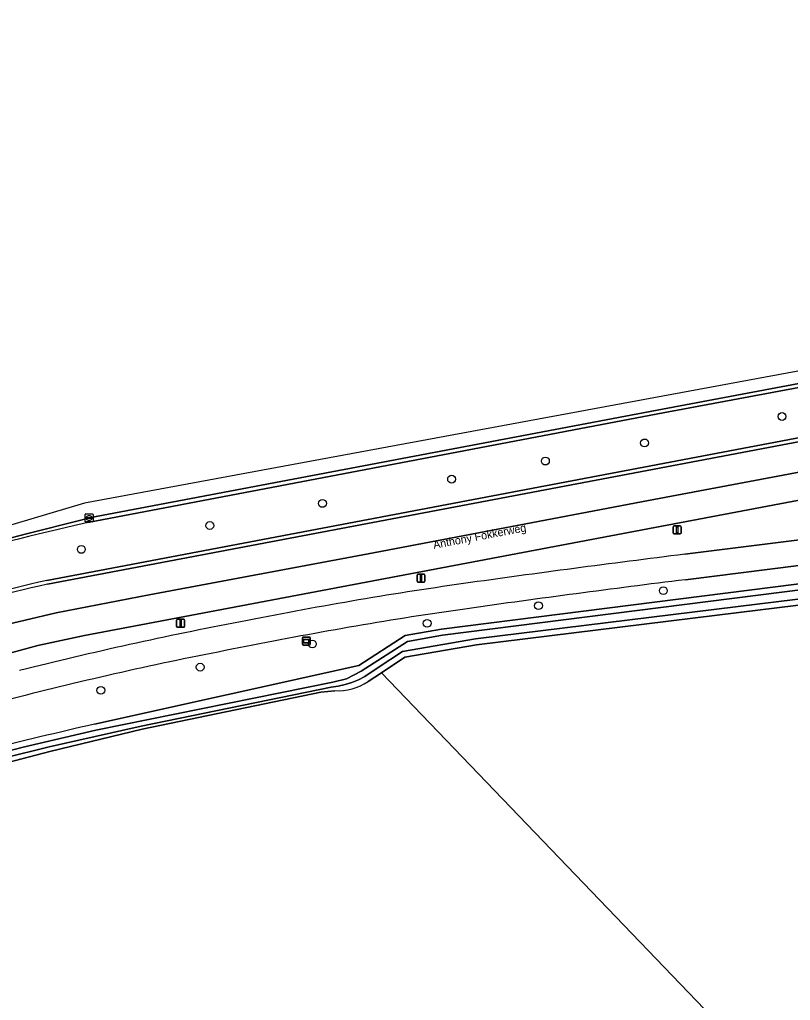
# Model space of a CAD drawing. Extents: x 157132 to 159279, y 384991 to 386650.
# Drawn here: x 157669 to 157765.4, y 386347.4 to 386470 of the extents above; entities that cross this region are included whole.
import ezdxf

# ---------------------------------------------------------------- set-up
doc = ezdxf.new("R2010")
doc.units = 0
for name, color, linetype in [('IMGEO_Berm_groen', 7, 'Continuous'), ('IMGEO_Berm_open', 7, 'Continuous'), ('IMGEO_Boom', 7, 'Continuous'), ('IMGEO_Bouwland', 7, 'Continuous'), ('IMGEO_Fietspad_open', 7, 'Continuous'), ('IMGEO_Groenvoorziening', 7, 'Continuous'), ('IMGEO_Kolk', 7, 'Continuous'), ('IMGEO_Lichtmast', 7, 'Continuous'), ('IMGEO_Loofbos', 7, 'Continuous'), ('IMGEO_Oever', 7, 'Continuous'), ('IMGEO_Openbare_ruimte_label', 7, 'Continuous'), ('IMGEO_Rijbaan_regionaal_gesloten', 7, 'Continuous'), ('IMGEO_Verklikker', 7, 'Continuous'), ('IMGEO_Waterloop', 7, 'Continuous')]:
    doc.layers.add(name, color=color, linetype=linetype)

msp = doc.modelspace()

# ---------------------------------------------------------------- linework, layer by layer
at = {"layer": 'IMGEO_Berm_groen'}
for points in [[(157813.78, 386432.88), (157748.87, 386420.72), (157677.57, 386407.16)], [(157672.45, 386399.91), (157816.05, 386427.15)], [(157843.77, 386421.91), (157840.21, 386420.94), (157837.53, 386420.52), (157807.76, 386417.47), (157804.84, 386417.18), (157677.17, 386393.04), (157671.33, 386391.76), (157661.82, 386389.18), (157654.52, 386387.21), (157643.11, 386383.56), (157641.3, 386382.98), (157629.56, 386378.95), (157619.91, 386375.39), (157605.44, 386369.88), (157598.41, 386367.06), (157586.87, 386361.94)], [(157752.22, 386403.2), (157786.88, 386407.53), (157833.7, 386413.41)]]:
    msp.add_lwpolyline(points, dxfattribs=at)
for centre, radius, start, end in [((157790.4, 385918.61), 501.41, 103.0044, 107.6634), ((157993.4, 384480.42), 1937.84, 97.14941, 97.97507), ((157771.77, 385969.6), 441.63, 102.9972, 107.3297), ((157794.41, 385908.3), 496.16, 98.0956, 101.363), ((157786.26, 385923.76), 479.43, 100.7721, 104.1519)]:
    msp.add_arc(centre, radius, start, end, dxfattribs=at)
at = {"layer": 'IMGEO_Berm_open'}
for points in [[(157921.21, 386470.01), (157894.12, 386457.52), (157865.93, 386446.88), (157837.1, 386438.58), (157813.68, 386433.39), (157748.77, 386421.2), (157677.74, 386407.72), (157676.87, 386407.48), (157669.9, 386405.73), (157663.33, 386404.02), (157660.03, 386403.12), (157650.63, 386400.53), (157647.58, 386399.62), (157640.8, 386397.6), (157638.12, 386396.74), (157629.98, 386394.14), (157623.21, 386391.87), (157613.38, 386388.34), (157610.21, 386387.16), (157600.92, 386383.53), (157598.68, 386382.58), (157589.94, 386378.98)], [(157677.57, 386407.16), (157748.87, 386420.72), (157813.78, 386432.88)], [(157672.51, 386399.46), (157816.13, 386426.67), (157825.96, 386428.65), (157835.9, 386430.97)], [(157825.85, 386429.16), (157816.05, 386427.15), (157672.45, 386399.91)]]:
    msp.add_lwpolyline(points, dxfattribs=at)
for centre, radius, start, end in [((157790.4, 385918.61), 501.41, 103.0044, 107.6634), ((157771.77, 385969.6), 441.63, 102.9972, 107.3297), ((157770.41, 385975.21), 435.39, 102.9944, 107.3754)]:
    msp.add_arc(centre, radius, start, end, dxfattribs=at)
at = {"layer": 'IMGEO_Boom'}
for centre in [(157764.38, 386420.4), (157747.19, 386417.1), (157734.79, 386414.83), (157723.06, 386412.57), (157706.91, 386409.54), (157692.83, 386406.77), (157676.76, 386403.79), (157749.53, 386398.63), (157733.92, 386396.75), (157720, 386394.55), (157705.65, 386391.96), (157691.62, 386389.07), (157679.2, 386386.17)]:
    msp.add_circle(centre, 0.489, dxfattribs=at)
at = {"layer": 'IMGEO_Bouwland'}
for points in [[(157714.3, 386388.38), (157712.61, 386387.26)], [(157800.01, 386296.82), (157801.18, 386297.94), (157714.3, 386388.38)], [(157708.44, 386386.13), (157706.71, 386385.94), (157684.36, 386381.3), (157672.84, 386378.51), (157661.47, 386375.55)]]:
    msp.add_lwpolyline(points, dxfattribs=at)
msp.add_arc((157708.88, 386392.77), 6.65, 266.2635, 304.121, dxfattribs=at)
at = {"layer": 'IMGEO_Fietspad_open'}
for points in [[(157752.3, 386400), (157787.26, 386404.39), (157831.97, 386409.98), (157846.47, 386412.19), (157877, 386416.04)], [(157833.7, 386413.41), (157786.88, 386407.53), (157752.22, 386403.2)]]:
    msp.add_lwpolyline(points, dxfattribs=at)
for centre, radius, start, end in [((157993.4, 384480.42), 1937.84, 97.14941, 97.97507), ((157954.91, 384768.71), 1643.83, 97.07995, 98.04006), ((157794.41, 385908.3), 496.16, 98.0956, 101.363), ((157794.39, 385908.46), 492.83, 98.0942, 101.358), ((157786.26, 385923.76), 479.43, 100.7721, 104.1519), ((157781.31, 385945.65), 453.82, 100.6636, 104.2298), ((157811.65, 385852.76), 551.36, 104.9133, 107.8447)]:
    msp.add_arc(centre, radius, start, end, dxfattribs=at)
at = {"layer": 'IMGEO_Groenvoorziening'}
for points in [[(157932.97, 386423.37), (157892.32, 386418.11), (157877, 386416.04), (157846.47, 386412.19), (157831.97, 386409.98), (157787.26, 386404.39), (157752.3, 386400)], [(157678.41, 386381.94), (157711.46, 386389.29), (157717.26, 386393.02), (157721.8, 386393.84), (157916.46, 386418.5), (157920.27, 386418.98)]]:
    msp.add_lwpolyline(points, dxfattribs=at)
for centre, radius, start, end in [((157954.91, 384768.71), 1643.83, 97.07995, 98.04006), ((157794.39, 385908.46), 492.83, 98.0942, 101.358), ((157781.31, 385945.65), 453.82, 100.6636, 104.2298), ((157811.65, 385852.76), 551.36, 104.9133, 107.8447), ((157787.04, 385903.02), 491.09, 102.7805, 106.0498)]:
    msp.add_arc(centre, radius, start, end, dxfattribs=at)
at = {"layer": 'IMGEO_Kolk'}
for p, q in [((157677.23, 386407.29), (157677.23, 386408.14)), ((157677.31, 386408.22), (157678.16, 386408.22)), ((157678.16, 386407.22), (157677.31, 386407.22)), ((157677.49, 386407.71), (157677.49, 386407.72)), ((157677.93, 386407.67), (157677.53, 386407.67)), ((157677.54, 386407.76), (157677.93, 386407.76)), ((157677.72, 386408), (157677.75, 386408)), ((157677.74, 386407.44), (157677.72, 386407.44)), ((157677.98, 386407.72), (157677.98, 386407.71)), ((157678.24, 386408.14), (157678.24, 386407.29))]:
    msp.add_line(p, q, dxfattribs=at)
for points in [[(157677.23, 386407.29), (157677.23, 386408.14)], [(157677.31, 386408.22), (157678.16, 386408.22)], [(157678.16, 386407.22), (157677.31, 386407.22)], [(157678.24, 386408.14), (157678.24, 386407.29)]]:
    msp.add_lwpolyline(points, dxfattribs=at)
for centre, radius, start, end in [((157677.31, 386408.14), 0.0765, 91.552, 178.448), ((157677.31, 386408.14), 0.0765, 91.552, 178.448), ((157677.31, 386407.29), 0.0765, 181.552, 268.448), ((157677.31, 386407.29), 0.0765, 181.552, 268.448), ((157677.53, 386407.72), 0.0403, 85.8775, 175.7526), ((157677.53, 386407.71), 0.0366, 178.938, 274.7102), ((157677.94, 386407.72), 0.0386, 1.7309, 96.639), ((157677.93, 386407.72), 0.043, 264.8664, 352.4533), ((157678.16, 386408.14), 0.0765, 1.552, 88.448), ((157678.16, 386408.14), 0.0765, 1.552, 88.448), ((157678.16, 386407.29), 0.0765, 271.552, 358.448), ((157678.16, 386407.29), 0.0765, 271.552, 358.448)]:
    msp.add_arc(centre, radius, start, end, dxfattribs=at)
for centre, major_axis, ratio, start_param, end_param in [((157677.72, 386407.72), (-0.387, 0.002), 0.722429, 4.712389, 7.853982), ((157677.75, 386407.72), (-0.39, 0.002), 0.717154, 1.570796, 4.712389)]:
    msp.add_ellipse(centre, major_axis=major_axis, ratio=ratio, start_param=start_param, end_param=end_param, dxfattribs=at)
at = {"layer": 'IMGEO_Lichtmast'}
for p, q in [((157750.77, 386405.83), (157750.77, 386406.63)), ((157750.77, 386406.63), (157750.77, 386405.83)), ((157750.87, 386406.73), (157751.66, 386406.73)), ((157751.66, 386406.73), (157750.87, 386406.73)), ((157751.76, 386406.63), (157751.76, 386405.83)), ((157751.76, 386405.83), (157751.76, 386406.63)), ((157751.66, 386405.73), (157750.87, 386405.73)), ((157750.87, 386405.73), (157751.66, 386405.73)), ((157718.74, 386399.8), (157718.74, 386400.59)), ((157718.74, 386400.59), (157718.74, 386399.8)), ((157718.84, 386400.69), (157719.63, 386400.69)), ((157719.63, 386400.69), (157718.84, 386400.69)), ((157719.63, 386399.7), (157718.84, 386399.7)), ((157718.84, 386399.7), (157719.63, 386399.7)), ((157719.73, 386400.59), (157719.73, 386399.8)), ((157719.73, 386399.8), (157719.73, 386400.59)), ((157688.68, 386394.15), (157688.68, 386394.95)), ((157688.68, 386394.95), (157688.68, 386394.15)), ((157688.78, 386395.05), (157689.57, 386395.05)), ((157689.57, 386395.05), (157688.78, 386395.05)), ((157689.67, 386394.95), (157689.67, 386394.15)), ((157689.67, 386394.15), (157689.67, 386394.95)), ((157689.57, 386394.05), (157688.78, 386394.05)), ((157688.78, 386394.05), (157689.57, 386394.05))]:
    msp.add_line(p, q, dxfattribs=at)
for points in [[(157751.19, 386406.61), (157751.34, 386406.61), (157751.34, 386405.86), (157751.19, 386405.86), (157751.19, 386406.61)], [(157719.16, 386400.57), (157719.31, 386400.57), (157719.31, 386399.82), (157719.16, 386399.82), (157719.16, 386400.57)], [(157689.1, 386394.93), (157689.25, 386394.93), (157689.25, 386394.18), (157689.1, 386394.18), (157689.1, 386394.93)]]:
    msp.add_lwpolyline(points, dxfattribs=at)
for centre, start, end in [((157750.87, 386406.63), 90, 180), ((157750.87, 386406.63), 90, 180), ((157750.87, 386405.83), 180, 270), ((157750.87, 386405.83), 180, 270), ((157751.66, 386406.63), 0, 90), ((157751.66, 386406.63), 360, 90), ((157751.66, 386405.83), 270, 0), ((157751.66, 386405.83), 270, 0), ((157718.84, 386400.59), 90, 180), ((157718.84, 386400.59), 90, 180), ((157718.84, 386399.8), 180, 270), ((157718.84, 386399.8), 180, 270), ((157719.63, 386400.59), 0, 90), ((157719.63, 386400.59), 360, 90), ((157719.63, 386399.8), 270, 0), ((157719.63, 386399.8), 270, 0), ((157688.78, 386394.95), 90, 180), ((157688.78, 386394.95), 90, 180), ((157689.57, 386394.95), 0, 90), ((157689.57, 386394.95), 360, 90), ((157688.78, 386394.15), 180, 270), ((157688.78, 386394.15), 180, 270), ((157689.57, 386394.15), 270, 0), ((157689.57, 386394.15), 270, 0)]:
    msp.add_arc(centre, 0.1, start, end, dxfattribs=at)
at = {"layer": 'IMGEO_Loofbos'}
msp.add_lwpolyline([(157837.47, 386383.66), (157834.68, 386391.91), (157834.68, 386395.9), (157849.97, 386400.56), (157850.89, 386407.19), (157756.29, 386395.57), (157726.18, 386391.88), (157717.22, 386390.31), (157714.3, 386388.38), (157801.18, 386297.94), (157826.05, 386321.69), (157878.21, 386371.54), (157880.42, 386373.63), (157881.46, 386374.61), (157903.82, 386395.75), (157921.13, 386413.3)], dxfattribs=at)
at = {"layer": 'IMGEO_Oever'}
for points in [[(157712.61, 386387.26), (157714.3, 386388.38), (157717.22, 386390.31), (157726.18, 386391.88), (157756.29, 386395.57), (157850.89, 386407.19), (157881.49, 386410.95), (157917.19, 386415.33), (157917.78, 386416.17), (157917.58, 386417.87), (157916.46, 386418.5), (157721.8, 386393.84), (157717.26, 386393.02), (157711.46, 386389.29), (157678.41, 386381.94)], [(157660.47, 386376.73), (157669.5, 386379.05), (157678.58, 386381.2), (157708.19, 386387.21), (157709.91, 386387.6), (157711.76, 386388.58), (157717.54, 386392.29), (157721.92, 386393.09), (157915.68, 386417.63)], [(157850.8, 386407.94), (157756.2, 386396.32), (157726.07, 386392.63), (157716.93, 386391.03), (157713.88, 386389.01), (157712.21, 386387.91), (157711.42, 386387.5), (157710.6, 386387.16), (157709.75, 386386.89), (157708.88, 386386.7), (157707.99, 386386.59), (157684.26, 386381.68), (157672.74, 386379.11), (157661.28, 386376.29)], [(157661.47, 386375.55), (157672.84, 386378.51), (157684.36, 386381.3), (157706.71, 386385.94), (157708.44, 386386.13)]]:
    msp.add_lwpolyline(points, dxfattribs=at)
for centre, radius, start, end in [((157708.88, 386392.77), 6.65, 266.2635, 304.121), ((157787.04, 385903.02), 491.09, 102.7805, 106.0498)]:
    msp.add_arc(centre, radius, start, end, dxfattribs=at)
at = {"layer": 'IMGEO_Rijbaan_regionaal_gesloten'}
for points in [[(157813.46, 386434.79), (157677.15, 386409.57), (157651.09, 386401.83), (157605.48, 386388.3), (157523.83, 386347.69)], [(157589.94, 386378.98), (157598.68, 386382.58), (157600.92, 386383.53), (157610.21, 386387.16), (157613.38, 386388.34), (157623.21, 386391.87), (157629.98, 386394.14), (157638.12, 386396.74), (157640.8, 386397.6), (157647.58, 386399.62), (157650.63, 386400.53), (157660.03, 386403.12), (157663.33, 386404.02), (157669.9, 386405.73), (157676.87, 386407.48), (157677.74, 386407.72), (157748.77, 386421.2), (157813.68, 386433.39)], [(157835.9, 386430.97), (157825.96, 386428.65), (157816.13, 386426.67), (157672.51, 386399.46)], [(157586.87, 386361.94), (157598.41, 386367.06), (157605.44, 386369.88), (157619.91, 386375.39), (157629.56, 386378.95), (157641.3, 386382.98), (157643.11, 386383.56), (157654.52, 386387.21), (157661.82, 386389.18), (157671.33, 386391.76), (157677.17, 386393.04), (157804.84, 386417.18)], [(157587.17, 386366.22), (157601.75, 386372.59), (157616.54, 386378.44), (157631.47, 386383.82), (157642.84, 386387.53), (157654.3, 386390.99), (157661.94, 386393.12), (157673.63, 386395.85), (157685.26, 386398.11), (157712.63, 386403.25), (157747.69, 386409.91), (157767.4, 386413.63)], [(157767.4, 386413.63), (157747.69, 386409.91), (157712.63, 386403.25), (157685.26, 386398.11), (157673.63, 386395.85), (157661.94, 386393.12), (157654.3, 386390.99), (157642.84, 386387.53), (157631.47, 386383.82), (157616.54, 386378.44), (157601.75, 386372.59), (157587.17, 386366.22)]]:
    msp.add_lwpolyline(points, dxfattribs=at)
msp.add_arc((157770.41, 385975.21), 435.39, 102.9944, 107.3754, dxfattribs=at)
at = {"layer": 'IMGEO_Verklikker'}
for p, q in [((157704.4, 386391.93), (157704.4, 386392.73)), ((157704.4, 386392.73), (157704.4, 386391.93)), ((157704.5, 386392.83), (157705.29, 386392.83)), ((157705.29, 386392.83), (157704.5, 386392.83)), ((157705.39, 386392.73), (157705.39, 386391.93)), ((157705.39, 386391.93), (157705.39, 386392.73)), ((157705.29, 386391.83), (157704.5, 386391.83)), ((157704.5, 386391.83), (157705.29, 386391.83))]:
    msp.add_line(p, q, dxfattribs=at)
for points in [[(157704.5, 386392.56), (157705.28, 386392.56), (157705.28, 386392.09), (157704.5, 386392.09), (157704.5, 386392.56)], [(157704.56, 386392.49), (157704.56, 386392.16), (157705.22, 386392.16), (157705.22, 386392.49), (157704.56, 386392.49)]]:
    msp.add_lwpolyline(points, dxfattribs=at)
for centre, start, end in [((157704.5, 386392.73), 90, 180), ((157704.5, 386392.73), 90, 180), ((157705.29, 386392.73), 0, 90), ((157705.29, 386392.73), 360, 90), ((157704.5, 386391.93), 180, 270), ((157704.5, 386391.93), 180, 270), ((157705.29, 386391.93), 270, 0), ((157705.29, 386391.93), 270, 0)]:
    msp.add_arc(centre, 0.1, start, end, dxfattribs=at)
at = {"layer": 'IMGEO_Waterloop'}
for points in [[(157915.68, 386417.63), (157721.92, 386393.09), (157717.54, 386392.29), (157711.76, 386388.58), (157709.91, 386387.6), (157708.19, 386387.21), (157678.58, 386381.2), (157669.5, 386379.05), (157660.47, 386376.73)], [(157661.28, 386376.29), (157672.74, 386379.11), (157684.26, 386381.68), (157707.99, 386386.59), (157708.88, 386386.7), (157709.75, 386386.89), (157710.6, 386387.16), (157711.42, 386387.5), (157712.21, 386387.91), (157713.88, 386389.01), (157716.93, 386391.03), (157726.07, 386392.63), (157756.2, 386396.32), (157850.8, 386407.94)]]:
    msp.add_lwpolyline(points, dxfattribs=at)

# ---------------------------------------------------------------- texts
at = {"layer": 'IMGEO_Openbare_ruimte_label'}
msp.add_text('Anthony Fokkerweg', height=1, rotation=10.7816, dxfattribs=at).set_placement((157720.85, 386403.85))

doc.saveas('drawing.dxf')
